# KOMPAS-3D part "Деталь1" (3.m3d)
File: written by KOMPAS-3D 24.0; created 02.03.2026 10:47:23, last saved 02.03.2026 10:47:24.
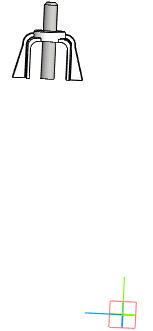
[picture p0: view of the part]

Document properties: Автор: R2D2; Полное имя файла: E:\Работа\Зайцев\GVWR3131M-2W-F-S Задвижка клиновая с выдвижным штоком DN.ru Ду50-200 Ру63\DN200\исходные материалы\3.m3d

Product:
- Body: Твердое тело1  | qty 1
    Масса: 1.56108
- Part/product: Деталь1
    Масса: 1.56108
    additional columns: Типовые

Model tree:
1. Твердое тело1  (labels: Твердое тело1)
2. Эскиз:1
3. Элемент выдавливания:1
     Расстояние 1 = 500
